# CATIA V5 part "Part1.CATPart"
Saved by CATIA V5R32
Part number: Part1
Bounding box of the stored display mesh (mm): x 0 to 20, y -150 to 150, z -40 to 40
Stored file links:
  D:\PROJECTS\Project 2022\CATIA V5 6R 2022\Resources\Part Files\c16_catia_v5_6r2022_prt\Slide Curve Joint-(Fig16-40)\Part1.CATPart
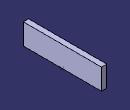
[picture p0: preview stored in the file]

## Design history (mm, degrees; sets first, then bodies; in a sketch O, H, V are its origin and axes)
Body1 (main body)
  Sketch1 on yz-plane, origin (0, 0, 0), H (0, 1, 0), V (0, 0, 1)
    line L1 (150, 40) -> (150, -40)
    line L2 (150, -40) -> (-150, -40)
    line L3 (-150, -40) -> (-150, 40)
    line L4 (-150, 40) -> (150, 40)
    length L4 = 300
    length L1 = 80
    vertical: L1 V, L3 V
    horizontal: L2 H, L4 H
    equidistance: L1 L3 O, L2 L4 O
  Pad1: profile Sketch1, direction (1, 0, 0), length 20
  Point1: type OnCurve, Support edge [face of Pad1 from Sketch1.L2 | end face of Pad1], Ratio 0.5
  Sketch2 on zx-plane, origin (0, 0, 0), H (-1, 0, 0), V (0, 0, 1)
    line L1 (-75, -185) -> (75, -185)
    point P1 (-75, -185)
    distance L1 H = 185
    length L1 = 150
    distance V P1 = 75
    horizontal: L1 H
